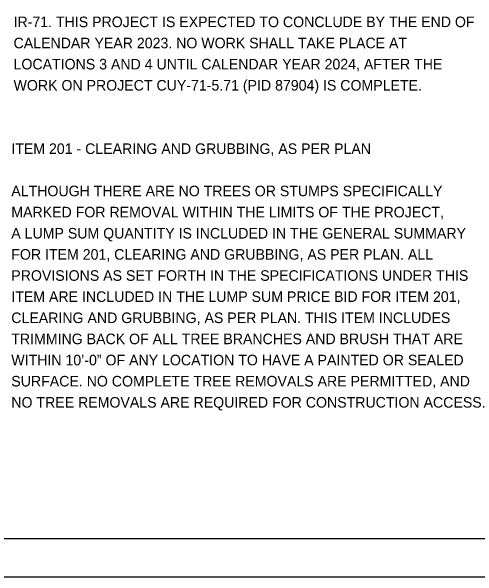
# Model space of a CAD drawing. Extents: x 0 to 34, y -14.6 to 28.2.
# Drawn here: x 24.66 to 30.84, y 0 to 7.49 of the extents above; entities that cross this region are included whole.
import ezdxf

# ---------------------------------------------------------------- set-up
doc = ezdxf.new("R2010")
doc.units = 0
for name, color, linetype in [('SH_Border', 7, 'Continuous'), ('SH_Cut_Line', 7, 'Continuous'), ('SH_Text', 7, 'Continuous')]:
    doc.layers.add(name, color=color, linetype=linetype)

msp = doc.modelspace()

# ---------------------------------------------------------------- linework, layer by layer
at = {"layer": 'SH_Border'}
msp.add_lwpolyline([(1.5, 21.5), (33.5, 21.5), (33.5, 0.5), (1.5, 0.5)], close=True, dxfattribs=at)
at = {"layer": 'SH_Cut_Line'}
msp.add_lwpolyline([(0, 0), (34, 0), (34, 22), (0, 22)], close=True, dxfattribs=at)

# ---------------------------------------------------------------- texts
at = {"layer": 'SH_Text'}
for s, p in [('IR-71. THIS PROJECT IS EXPECTED TO CONCLUDE BY THE END OF ', (24.69, 7.28)), ('CALENDAR YEAR 2023. NO WORK SHALL TAKE PLACE AT ', (24.69, 7)), ('LOCATIONS 3 AND 4 UNTIL CALENDAR YEAR 2024, AFTER THE ', (24.69, 6.72)), ('WORK ON PROJECT CUY-71-5.71 (PID 87904) IS COMPLETE.', (24.69, 6.44)), ('ITEM 201 - CLEARING AND GRUBBING, AS PER PLAN', (24.66, 5.6)), ('ALTHOUGH THERE ARE NO TREES OR STUMPS SPECIFICALLY ', (24.66, 5.04)), ('MARKED FOR REMOVAL WITHIN THE LIMITS OF THE PROJECT, ', (24.66, 4.76)), ('A LUMP SUM QUANTITY IS INCLUDED IN THE GENERAL SUMMARY ', (24.66, 4.48)), ('FOR ITEM 201, CLEARING AND GRUBBING, AS PER PLAN. ALL ', (24.66, 4.2)), ('PROVISIONS AS SET FORTH IN THE SPECIFICATIONS UNDER THIS ', (24.66, 3.92)), ('ITEM ARE INCLUDED IN THE LUMP SUM PRICE BID FOR ITEM 201, ', (24.66, 3.64)), ('CLEARING AND GRUBBING, AS PER PLAN. THIS ITEM INCLUDES ', (24.66, 3.36)), ('TRIMMING BACK OF ALL TREE BRANCHES AND BRUSH THAT ARE ', (24.66, 3.08)), ('WITHIN 10’-0” OF ANY LOCATION TO HAVE A PAINTED OR SEALED ', (24.66, 2.8)), ('SURFACE. NO COMPLETE TREE REMOVALS ARE PERMITTED, AND ', (24.66, 2.52)), ('NO TREE REMOVALS ARE REQUIRED FOR CONSTRUCTION ACCESS.', (24.66, 2.24))]:
    msp.add_text(s, height=0.14, dxfattribs=at).set_placement(p)

doc.saveas('drawing.dxf')
